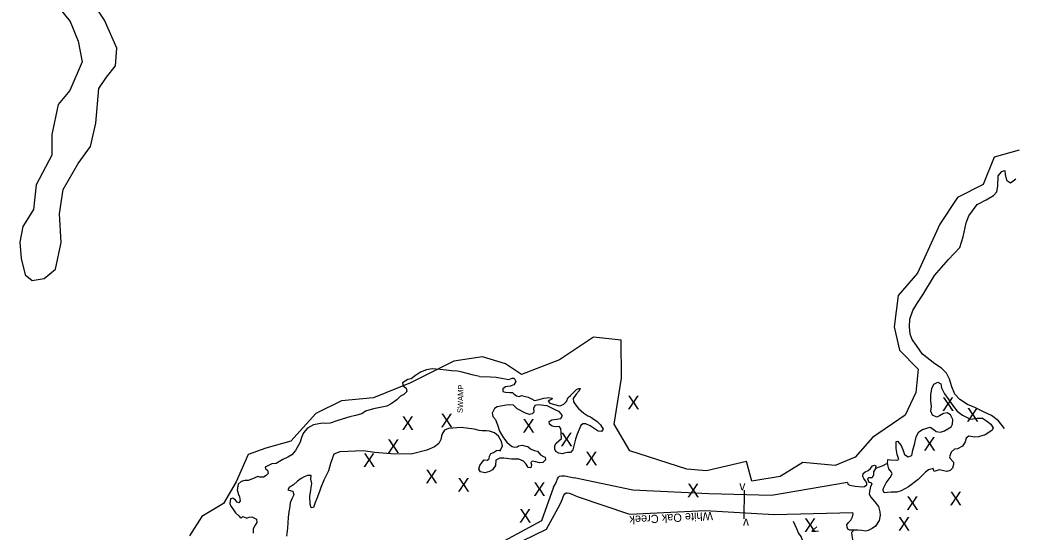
# Model space of a CAD drawing. Extents: x 2030130 to 2036320, y 723205 to 762423.
# Drawn here: x 2033676 to 2034406, y 738120 to 738494 of the extents above; entities that cross this region are included whole.
import ezdxf

# ---------------------------------------------------------------- set-up
doc = ezdxf.new("R2010")
doc.units = 0
for name, color, linetype in [('Draft_Station Tics Major', 7, 'Continuous'), ('Draft_Station Tics Minor', 7, 'Continuous'), ('Prop Alignment Horizontal', 7, 'Continuous'), ('Prop Alignment Vertical', 7, 'Continuous')]:
    doc.layers.add(name, color=color, linetype=linetype)

msp = doc.modelspace()

# ---------------------------------------------------------------- linework, layer by layer
at = {"layer": 'Draft_Station Tics Major'}
for points in [[(2033703.25, 738504.86), (2033712.62, 738493.33), (2033718.37, 738478.84), (2033721.33, 738463.75), (2033712.3, 738442.73), (2033703.78, 738432.64), (2033699.08, 738410.74), (2033699.15, 738395.58), (2033687.6, 738373.83), (2033685.76, 738355.95), (2033677.98, 738343.34), (2033675.88, 738331.92), (2033676.81, 738320.04), (2033679.58, 738308.12), (2033684.75, 738303.92), (2033693.48, 738305.31), (2033701.8, 738312.25), (2033706.05, 738331.66), (2033704.8, 738352.77), (2033707.56, 738370.49), (2033718.52, 738389.49), (2033727.49, 738401.95), (2033731.28, 738418.86), (2033733.56, 738444.38), (2033739.14, 738452.56), (2033745.78, 738460.98), (2033746.72, 738473.87), (2033737.68, 738494.23), (2033729.89, 738505.86)], [(2034406.21, 738399.15), (2034388.04, 738394.01), (2034380.09, 738374.02), (2034361.3, 738364.67), (2034348.35, 738345.19), (2034332.01, 738309.3), (2034317.95, 738293), (2034314.94, 738270.14), (2034318.78, 738252.92), (2034332.58, 738239.04), (2034330.89, 738221.94), (2034322.89, 738205.51), (2034299.07, 738189.16), (2034286.5, 738174.81), (2034271.73, 738168.67), (2034248.19, 738170.77), (2034231.62, 738160.59), (2034210.85, 738157.22), (2034207.08, 738171.67), (2034177.81, 738164.8), (2034163.47, 738166.04), (2034121.72, 738179.47), (2034110.15, 738198.84), (2034115.5, 738232.46), (2034115.32, 738260.4), (2034095.2, 738262.56), (2034070.32, 738245.97), (2034042.41, 738235.11), (2034030.72, 738243.01), (2034014.09, 738247.99), (2033993.07, 738245.03), (2033961.48, 738228.98), (2033934.22, 738218.11), (2033910.85, 738215.98), (2033892.06, 738206.64), (2033873.83, 738186.48), (2033855.65, 738181.21), (2033842.77, 738176.62), (2033834.03, 738156.64), (2033824.59, 738140.77), (2033808.7, 738131.37), (2033799.69, 738117.2)]]:
    msp.add_lwpolyline(points, dxfattribs=at)
at = {"layer": 'Draft_Station Tics Minor'}
msp.add_lwpolyline([(2034205.16, 738129.68), (2034205.45, 738150.48)], dxfattribs=at)
at = {"layer": 'Prop Alignment Horizontal'}
for points in [[(2034395.66, 738195.64), (2034391.27, 738201.18), (2034386.05, 738205.15), (2034380.79, 738207.52), (2034373.83, 738210.99), (2034368.43, 738213.23), (2034362.94, 738216.94), (2034359.31, 738220.73), (2034357.03, 738226.1), (2034355.3, 738231.84), (2034353.14, 738236.27), (2034349.64, 738239.93), (2034344.66, 738243.09), (2034335.65, 738249.93), (2034331.14, 738256.4), (2034328.05, 738260.72), (2034326.55, 738264.73), (2034326.13, 738270.05), (2034326.39, 738275.76), (2034328.65, 738281.95), (2034332.09, 738287.58), (2034335.81, 738293.47), (2034344.48, 738307.49), (2034354.56, 738319.22), (2034362.85, 738328.06), (2034365.28, 738335.84), (2034367.63, 738346.02), (2034369.6, 738351.28), (2034375.62, 738359.38), (2034382.07, 738362.96), (2034387.45, 738366.03), (2034389.9, 738368.76), (2034390.78, 738372.86), (2034390.95, 738380.42), (2034393.54, 738383.68), (2034395.95, 738384.3), (2034396.15, 738381.37), (2034396.99, 738377.37), (2034399.86, 738375.32), (2034403.78, 738378.28)], [(2034011.74, 738233.82), (2034007.41, 738234.64), (2034002.7, 738235.86), (2033999.1, 738236.92), (2033995.76, 738237.59), (2033991.23, 738237.89), (2033987.42, 738238.43), (2033982.83, 738238.93), (2033977.18, 738239.31), (2033973.15, 738238.61), (2033968.63, 738236.93), (2033964.96, 738234.45), (2033961.88, 738232.08), (2033959.3, 738231.54), (2033955.63, 738229.19), (2033955.97, 738226.88), (2033958.17, 738225.18), (2033958.71, 738222.74), (2033956.56, 738220.61), (2033954.16, 738219.22), (2033951.34, 738216.71), (2033947.26, 738213.71), (2033944.13, 738212), (2033934.41, 738209.98), (2033928.45, 738208.39), (2033925.78, 738206.35), (2033921.27, 738205.13), (2033916.98, 738204.24), (2033908.17, 738201.6), (2033902.66, 738199.55), (2033899.5, 738199.42), (2033897, 738199.61), (2033890.52, 738198.43), (2033886, 738196.03), (2033883.09, 738192.47), (2033881.7, 738189.15), (2033880.77, 738185.81), (2033877.28, 738179.5), (2033874.51, 738176.41), (2033871.78, 738174.82), (2033867.99, 738173.06), (2033863.12, 738170.14), (2033859.89, 738169.82), (2033855.23, 738167.35), (2033855.4, 738166.23), (2033856.89, 738165.27), (2033857.23, 738162.9), (2033855.75, 738161.28), (2033853.88, 738160.01), (2033851.25, 738160), (2033849.68, 738160.63), (2033845.96, 738158.8), (2033842.77, 738157.55), (2033840.27, 738157.74), (2033837.56, 738156.94), (2033835.34, 738154.89), (2033834.66, 738150.89), (2033835.71, 738147.51), (2033836.39, 738145.72), (2033836.85, 738142.74), (2033835.9, 738141.25), (2033834.66, 738141.74), (2033833.38, 738143.41), (2033831.56, 738144.77), (2033829.84, 738144.21), (2033829.37, 738140.93), (2033829.99, 738139.01), (2033831.46, 738136.87), (2033833.37, 738134.13), (2033835.89, 738131.77), (2033836.85, 738130.57), (2033837.83, 738130.42), (2033838.91, 738131.38), (2033841.25, 738130.41), (2033842.24, 738130.32), (2033843.44, 738130.89), (2033845.42, 738131.1), (2033848.74, 738129.45), (2033849.14, 738126.94), (2033847.92, 738125.06), (2033846.41, 738122.33), (2033846.27, 738119.11)], [(2034011.74, 738233.82), (2034019.89, 738233.57), (2034024.03, 738233.22), (2034027.83, 738232.41), (2034033.21, 738231.57), (2034035.66, 738232.44), (2034037.11, 738232.41), (2034038.31, 738229.95), (2034037.01, 738227.54), (2034034.29, 738226.74), (2034030.85, 738226.09), (2034028.92, 738224.75), (2034028.74, 738222.85), (2034030.7, 738222.15), (2034033.99, 738222.01), (2034035.83, 738221.97), (2034036.99, 738221.02), (2034038.8, 738219.54), (2034040.7, 738219.1), (2034042.43, 738219.72), (2034045.38, 738219.19), (2034047.47, 738218.49), (2034049.75, 738217.32), (2034052.03, 738216.28), (2034054.53, 738216.56), (2034058.84, 738217.85), (2034060.82, 738218.13), (2034062.14, 738218.3), (2034064.83, 738217.85), (2034064.62, 738217.06), (2034063.28, 738216.37), (2034062.02, 738215.8), (2034063.17, 738214.33), (2034065.72, 738213.42), (2034067.49, 738212.98), (2034069.78, 738212.34), (2034071.23, 738212.51), (2034073.42, 738213.51), (2034075.37, 738215.38), (2034076.69, 738218.25), (2034078.3, 738219.86), (2034079.85, 738221.4), (2034082.74, 738224.23), (2034084.33, 738224.92), (2034085.32, 738225.03), (2034084.56, 738223.27), (2034082.47, 738220.88), (2034080.16, 738217.58), (2034080.44, 738215.27), (2034082.67, 738211.93), (2034084.15, 738210.32), (2034088.09, 738206.94), (2034091.07, 738205.03), (2034093.03, 738204.26), (2034094.65, 738203.04), (2034097.76, 738200.8), (2034100.34, 738198.31), (2034102.31, 738195.18), (2034101.09, 738193.62), (2034098.59, 738193.74), (2034094.83, 738196.26), (2034092.82, 738197.75), (2034089.56, 738199.21), (2034087.32, 738199.06), (2034085.98, 738197.9), (2034083.08, 738191.58), (2034082.01, 738187.79), (2034080.72, 738183.14), (2034080, 738180.07), (2034078.24, 738178.26), (2034076.14, 738178.18), (2034074.02, 738177.76), (2034072.17, 738177.28), (2034069.81, 738177.59), (2034067.53, 738178.83), (2034066.78, 738180.49), (2034066.83, 738183.19), (2034067.73, 738185.01), (2034069.74, 738186.61), (2034071.82, 738188.47), (2034071.44, 738192.17), (2034071.19, 738195.66), (2034070.1, 738197.26), (2034067, 738196.94), (2034064.97, 738197.38), (2034062.97, 738198.87), (2034062.81, 738200.91), (2034064.75, 738201.99), (2034068.45, 738202.63), (2034071.28, 738203.03), (2034072.51, 738205.11), (2034070.15, 738208.12), (2034068.19, 738208.95), (2034061.29, 738212.33), (2034058.86, 738212.58), (2034054.85, 738213.06), (2034052.28, 738212.59), (2034051.17, 738210.38), (2034051.57, 738207.54), (2034050.36, 738206.38), (2034048.25, 738205.9)], [(2034309.15, 738155.88), (2034312.01, 738159.9), (2034313.52, 738162.51), (2034312.89, 738163.84), (2034310.96, 738166.12), (2034309.99, 738170.09), (2034310.19, 738172.99), (2034312.29, 738172.68), (2034316.77, 738172.58), (2034318.36, 738172.94), (2034317.12, 738176.79), (2034316.43, 738181.02), (2034316.28, 738186.3), (2034317.47, 738186.4), (2034320.03, 738183.18), (2034321.53, 738179.59), (2034322.53, 738176.8), (2034325.12, 738174.9), (2034327.78, 738175.9), (2034328.52, 738179.84), (2034329.95, 738184.94), (2034330.98, 738189.66), (2034332.9, 738193.18), (2034335.71, 738194.96), (2034341.28, 738196.69), (2034343.87, 738194.92), (2034345.69, 738193.43), (2034348.84, 738192.96), (2034351.76, 738194.08), (2034356.7, 738196.88), (2034357.66, 738198.83), (2034357.87, 738202.38), (2034356.23, 738205.58), (2034353.76, 738207.22), (2034351.11, 738206.62), (2034348.18, 738204.97), (2034346.18, 738204.09), (2034342.92, 738205.35), (2034341.8, 738208.27), (2034342.27, 738211.69), (2034341.7, 738215.92), (2034341.8, 738220.39), (2034342.42, 738224.99), (2034343.94, 738228.12), (2034346.87, 738229.51), (2034349.09, 738228.4), (2034349.55, 738225.36), (2034351.7, 738221.1), (2034354.89, 738216.55), (2034358.34, 738211.73), (2034361.04, 738208.38), (2034364.79, 738205.53), (2034370.66, 738202.63), (2034375.55, 738203.31), (2034379.63, 738203.23), (2034382.36, 738201.19), (2034385.6, 738198.75), (2034387.38, 738196.07), (2034386.69, 738194.37), (2034384.95, 738193.23), (2034381.34, 738191.07), (2034376.7, 738189.72), (2034373.8, 738189.39), (2034369.46, 738190.01), (2034367.45, 738188.6), (2034366.74, 738185.98), (2034364.95, 738182.73), (2034361.35, 738180.83), (2034358.98, 738180.62), (2034356.56, 738178.43)], [(2034048.25, 738205.9), (2034045.31, 738206.89), (2034039.45, 738210.11), (2034036.75, 738212.87), (2034032.87, 738213.02), (2034030.09, 738212.42), (2034024.81, 738211.62), (2034022.74, 738210.34), (2034021.02, 738206.96), (2034021.56, 738204.58), (2034023.55, 738202.23), (2034025.29, 738197.59), (2034026.33, 738193.75), (2034029.44, 738188.81), (2034031.68, 738185.6), (2034033.68, 738183.91), (2034035.69, 738182.55), (2034037.39, 738181.99), (2034039.24, 738182.28), (2034040.24, 738182.91), (2034042.95, 738183.58), (2034044.65, 738183.14), (2034047.08, 738182.5), (2034049.01, 738180.81), (2034051.68, 738179.5), (2034054.11, 738179.19), (2034056.29, 738176.51), (2034058.7, 738175.33), (2034059.87, 738174.78), (2034060.02, 738172.74), (2034058.01, 738170.94), (2034055.63, 738170.53), (2034052.95, 738171.31), (2034050.2, 738171.9), (2034049.25, 738170.8), (2034049.74, 738169.01), (2034049.24, 738166.92), (2034047.4, 738167.29), (2034045.87, 738169.56), (2034044.01, 738171.9), (2034040.62, 738173.23), (2034037.99, 738173.35), (2034035.09, 738173.35), (2034029.51, 738174), (2034026.62, 738173.93), (2034023.76, 738172.61), (2034023.54, 738168.73), (2034021.23, 738165.56), (2034019.17, 738164.35), (2034015.72, 738163.24), (2034012.58, 738163.97), (2034011.24, 738165.97), (2034012.09, 738168.52), (2034013.72, 738171.19), (2034015.27, 738172.73), (2034017.37, 738172.55), (2034018.84, 738173.51), (2034019.08, 738175.54), (2034020.18, 738177.43), (2034022.04, 738178.11), (2034024.3, 738179.51), (2034025.96, 738179.93), (2034026.8, 738179.26), (2034028.66, 738182.9), (2034028, 738186.08), (2034025.59, 738190.08), (2034022.68, 738192.64), (2034019.16, 738193.84), (2034016.66, 738194.09), (2034013.76, 738193.89), (2034011.53, 738194.2), (2034007.87, 738195.2), (2033998.41, 738196.4), (2033989.05, 738195.62), (2033986.2, 738194.56), (2033984.15, 738191.25), (2033983.48, 738187.71), (2033982.17, 738184.78), (2033978.89, 738182.35), (2033973.18, 738179.91), (2033961.79, 738176.93), (2033946.99, 738177.12), (2033935.36, 738178.04), (2033926.7, 738179.28), (2033915.5, 738178.86), (2033909.64, 738178.73), (2033905.26, 738176.98), (2033903, 738170.19), (2033901.43, 738164.63), (2033898, 738157.99), (2033895.84, 738152.64), (2033894.79, 738149.57), (2033892.83, 738144.48), (2033891.65, 738141.48), (2033890.38, 738137.95), (2033888.8, 738137.72), (2033888.13, 738140.3), (2033887.73, 738145.91), (2033888.42, 738150.5), (2033888.86, 738152.46), (2033889.19, 738155.55)], [(2034356.56, 738178.43), (2034355.3, 738175.03), (2034355.93, 738173.83), (2034358.37, 738171.01), (2034358.34, 738169.43), (2034357.62, 738166.68), (2034355.87, 738164.87), (2034353.48, 738164.14), (2034347.84, 738165.45), (2034344.13, 738164.34), (2034343.38, 738166.33), (2034339.93, 738165.35), (2034337.92, 738163.82), (2034332.53, 738158.4), (2034325.43, 738153.15), (2034319.97, 738150.11), (2034316.92, 738149.26), (2034312.83, 738149.08), (2034310.06, 738148.88), (2034307.54, 738148.54), (2034306.93, 738150.4), (2034307.1, 738152.11), (2034309.15, 738155.88)], [(2034310.25, 738169.48), (2034309.99, 738170.09), (2034308.8, 738169.59), (2034306.6, 738168.46), (2034301.29, 738166.53)], [(2034280.78, 738156.24), (2034280.98, 738154.94), (2034282.54, 738154.24), (2034286.35, 738153.5), (2034291.49, 738153.12), (2034293.21, 738153.35), (2034294.95, 738154.43), (2034294.84, 738155.69), (2034294.09, 738157.49), (2034292.68, 738159.17), (2034292.05, 738160.7), (2034292.36, 738162.73), (2034293.64, 738163.89), (2034296.03, 738164.9), (2034297.65, 738166.38), (2034299.14, 738168.39), (2034300.54, 738168.89), (2034301.45, 738168.47), (2034301.29, 738166.53), (2034299.84, 738163.92), (2034299.8, 738161.88), (2034298.76, 738159.66), (2034297.05, 738159.63), (2034296.06, 738159.72), (2034295.38, 738158.94), (2034296.31, 738156.35), (2034298.22, 738156.24), (2034298.59, 738155.05), (2034297.63, 738153.22), (2034296.89, 738149.74), (2034296.78, 738147.64), (2034297.86, 738145.44)], [(2033889.19, 738155.55), (2033888.6, 738158.53), (2033888.66, 738161.22), (2033886.16, 738161.34), (2033883.7, 738160.34), (2033881.44, 738159.21), (2033878.69, 738157.1), (2033875.88, 738154.59), (2033872.67, 738152.49), (2033871.78, 738150.8), (2033874.2, 738150.09), (2033875.24, 738149.8), (2033876.11, 738147.28), (2033874.8, 738144.74), (2033873.48, 738141.28), (2033872.99, 738137.21), (2033872.35, 738134.79), (2033871.86, 738130.66), (2033871.49, 738122.77), (2033870.71, 738116.93)], [(2034066, 738152.73), (2034067.02, 738154.86), (2034068.01, 738157.01), (2034068.81, 738158.81), (2034069.62, 738160.07), (2034070.25, 738160.78), (2034071.68, 738161.14), (2034074.11, 738160.96), (2034080.91, 738159.67)], [(2034280.78, 738156.24), (2034225.19, 738146.62), (2034179.55, 738147.81), (2034123.92, 738150.54), (2034080.91, 738159.67)], [(2034066, 738152.73), (2034057.08, 738128.21), (2034026.99, 738111.77), (2033988.61, 738098.76)], [(2034070.76, 738140.25), (2034071.77, 738142.65), (2034072.4, 738144.36), (2034072.85, 738145.79), (2034073.48, 738147.05), (2034074.11, 738147.95), (2034075.09, 738148.66), (2034075.99, 738148.75), (2034077.25, 738148.49), (2034078.86, 738147.86), (2034083.1, 738146.01)], [(2033991.65, 738091.61), (2034025.22, 738104.79), (2034060.8, 738122.09), (2034070.76, 738140.25)], [(2034083.1, 738146.01), (2034121.46, 738132.99), (2034176.7, 738135.69), (2034227.13, 738132.78), (2034284.68, 738134.3)], [(2034297.86, 738145.44), (2034300.81, 738142.01), (2034303.38, 738138.72), (2034304.55, 738134.87), (2034304.69, 738132.3), (2034304.01, 738128.35), (2034301.29, 738124.39), (2034298.74, 738122.47), (2034295.94, 738121.14), (2034293.95, 738120.59), (2034291.25, 738121.05), (2034288.43, 738121.37), (2034285.33, 738121.44), (2034282.56, 738121.44), (2034280.99, 738122.13), (2034280.49, 738123.53), (2034280.33, 738125.24), (2034281.49, 738127.07), (2034283.31, 738128.61), (2034284.55, 738131.09), (2034284.93, 738133.26), (2034284.68, 738134.3)], [(2034265.2, 738081.88), (2034261.15, 738086.52), (2034256.48, 738093.48), (2034252.14, 738099.84), (2034249.63, 738105.83), (2034248.55, 738110.47), (2034248.03, 738114.11), (2034246.91, 738116.84), (2034245.05, 738119.39), (2034243.66, 738122.32), (2034241.34, 738127.65), (2034241.31, 738127.77)], [(2034284.91, 738113.03), (2034284.21, 738117.39), (2034284, 738119.89), (2034285.33, 738121.44)]]:
    msp.add_lwpolyline(points, dxfattribs=at)

# ---------------------------------------------------------------- texts
at = {"layer": 'Draft_Station Tics Major'}
for p in [(2034119.88, 738209.64), (2034349.88, 738208.55), (2033983.34, 738196.58), (2034367.86, 738200.79), (2033954.89, 738194.58), (2034043.23, 738192.64), (2034070.98, 738182.75), (2033944.39, 738177.71), (2034336.36, 738179.51), (2033926.68, 738167.57), (2034089.13, 738168.75), (2033972.28, 738155.58), (2033995.72, 738149.49), (2034051.15, 738146.3), (2034163.55, 738145.47), (2034355.47, 738139.51), (2034323.84, 738136.12), (2034040.74, 738126.94), (2034249.04, 738120.01), (2034317.71, 738120.87)]:
    msp.add_text('X', height=10, dxfattribs=at).set_placement(p)
at = {"layer": 'Draft_Station Tics Minor'}
for rotation, p in [(359.43386, (2034201.71, 738150.52)), (178.95215, (2034208.9, 738129.61)), (290.75363, (2034253.69, 738122.53))]:
    msp.add_text('v', height=6.6, rotation=rotation, dxfattribs=at).set_placement(p)
at = {"layer": 'Prop Alignment Horizontal'}
msp.add_text('White Oak Creek', height=6, rotation=182.79505, dxfattribs=at).set_placement((2034182.3, 738134.69))
at = {"layer": 'Prop Alignment Vertical'}
msp.add_text('SWAMP', height=4, rotation=88.26387, dxfattribs=at).set_placement((2033999.55, 738206.91))

doc.saveas('drawing.dxf')
